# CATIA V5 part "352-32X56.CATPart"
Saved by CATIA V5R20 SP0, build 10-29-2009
Part number: 352-32X56
Definition: NONE
Nomenclature: 352-32X56
Source: Unknown
Description: 352-32X56
Bounding box of the stored display mesh (mm): x 0 to 56, y -20 to 20, z -20 to 20
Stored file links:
  C:\Users\Utente\Desktop\IO LAVORO\3D X SITO CF\X SITO\PLASTICA\352\352-32X56.CATPart
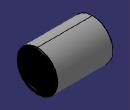
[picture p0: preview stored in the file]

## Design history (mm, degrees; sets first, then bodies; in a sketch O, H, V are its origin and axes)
Body1 "352-32X56" (main body)
  Solid1: solid without history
